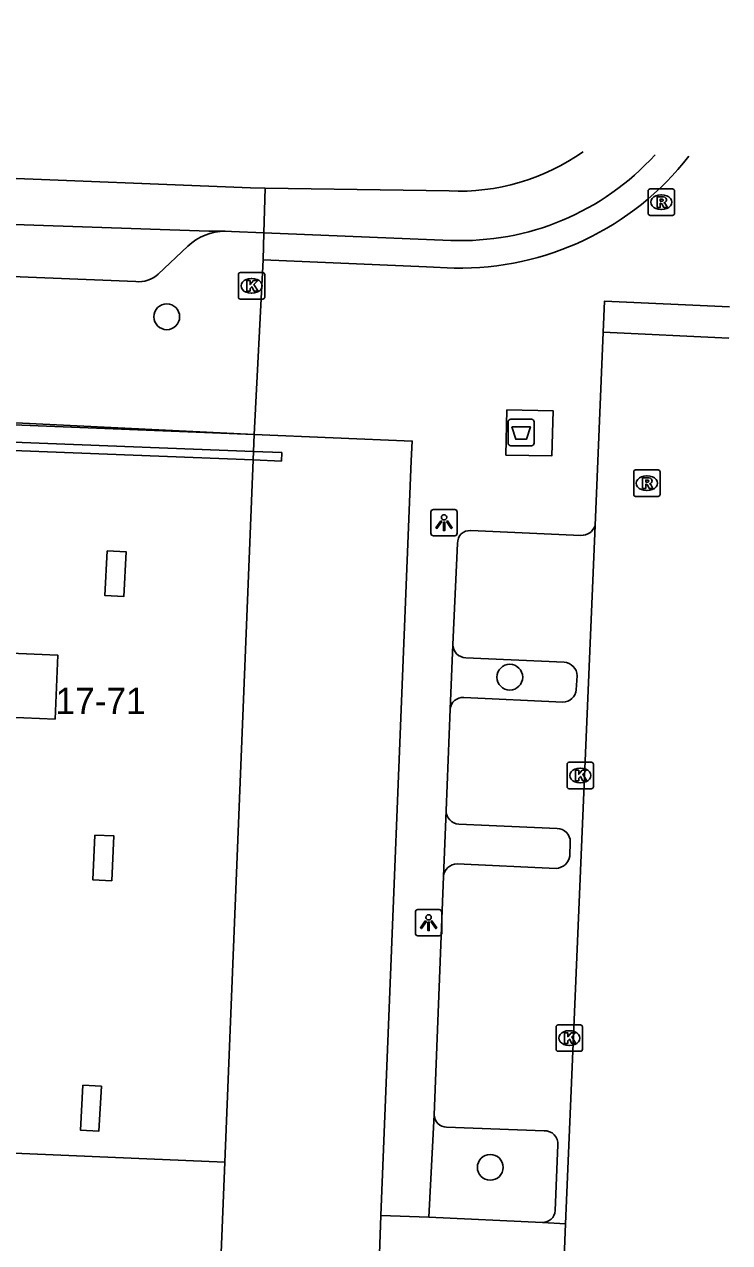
# Model space of a CAD drawing. Extents: x 160891 to 161384, y 386490 to 386907.
# Drawn here: x 161269.97 to 161296.73, y 386854.36 to 386900.56 of the extents above; entities that cross this region are included whole.
import ezdxf

# ---------------------------------------------------------------- set-up
doc = ezdxf.new("R2010")
doc.units = 0
for name, color, linetype in [('IMGEO_Afval_apart_plaats', 7, 'Continuous'), ('IMGEO_Boom', 7, 'Continuous'), ('IMGEO_Hek', 7, 'Continuous'), ('IMGEO_Kolk', 7, 'Continuous'), ('IMGEO_Lichtpunt', 7, 'Continuous'), ('IMGEO_Muur', 7, 'Continuous'), ('IMGEO_Pand', 7, 'Continuous'), ('IMGEO_Pand_nummerreeks', 7, 'Continuous'), ('IMGEO_Pand_overbouw', 7, 'Continuous'), ('IMGEO_Parkeervlak_open', 7, 'Continuous'), ('IMGEO_Rijbaan_lokaal_gesloten', 7, 'Continuous'), ('IMGEO_Rijbaan_lokaal_open', 7, 'Continuous'), ('IMGEO_Rioolput', 7, 'Continuous'), ('IMGEO_Voetpad_gesloten', 7, 'Continuous'), ('IMGEO_Voetpad_open', 7, 'Continuous')]:
    doc.layers.add(name, color=color, linetype=linetype)

msp = doc.modelspace()

# ---------------------------------------------------------------- linework, layer by layer
at = {"layer": 'IMGEO_Afval_apart_plaats'}
for p, q in [((161288.323, 386884.683), (161288.323, 386885.483)), ((161288.323, 386885.483), (161288.323, 386884.683)), ((161288.423, 386885.583), (161289.213, 386885.583)), ((161289.213, 386885.583), (161288.423, 386885.583)), ((161289.313, 386885.483), (161289.313, 386884.683)), ((161289.313, 386884.683), (161289.313, 386885.483)), ((161289.213, 386884.583), (161288.423, 386884.583)), ((161288.423, 386884.583), (161289.213, 386884.583))]:
    msp.add_line(p, q, dxfattribs=at)
msp.add_lwpolyline([(161288.466, 386885.297), (161289.17, 386885.297), (161289.021, 386884.827), (161288.615, 386884.827), (161288.466, 386885.297)], dxfattribs=at)
for centre, start, end in [((161288.423, 386885.483), 90, 180), ((161288.423, 386885.483), 90, 180), ((161289.213, 386885.483), 0, 90), ((161289.213, 386885.483), 360, 90), ((161288.423, 386884.683), 180, 270), ((161288.423, 386884.683), 180, 270), ((161289.213, 386884.683), 270, 0), ((161289.213, 386884.683), 270, 0)]:
    msp.add_arc(centre, 0.1, start, end, dxfattribs=at)
at = {"layer": 'IMGEO_Boom'}
for centre in [(161275.373, 386889.471), (161288.387, 386875.804), (161287.645, 386857.215)]:
    msp.add_circle(centre, 0.489, dxfattribs=at)
at = {"layer": 'IMGEO_Hek'}
msp.add_lwpolyline([(161284.645, 386884.014), (161283.497, 386855.383)], dxfattribs=at)
at = {"layer": 'IMGEO_Kolk'}
for p, q in [((161278.09, 386890.218), (161278.09, 386891.07)), ((161278.165, 386891.144), (161279.017, 386891.144)), ((161278.578, 386890.924), (161278.603, 386890.924)), ((161279.091, 386891.07), (161279.091, 386890.218)), ((161278.601, 386890.364), (161278.576, 386890.364)), ((161279.017, 386890.144), (161278.165, 386890.144)), ((161290.56, 386871.649), (161290.56, 386872.501)), ((161290.635, 386872.575), (161291.487, 386872.575)), ((161291.048, 386872.355), (161291.073, 386872.355)), ((161291.561, 386872.501), (161291.561, 386871.649)), ((161291.071, 386871.795), (161291.046, 386871.795)), ((161291.487, 386871.575), (161290.635, 386871.575)), ((161290.143, 386861.691), (161290.143, 386862.543)), ((161290.218, 386862.617), (161291.07, 386862.617)), ((161291.144, 386862.543), (161291.144, 386861.691)), ((161290.631, 386862.397), (161290.656, 386862.397)), ((161291.07, 386861.617), (161290.218, 386861.617)), ((161290.654, 386861.837), (161290.629, 386861.837))]:
    msp.add_line(p, q, dxfattribs=at)
for points in [[(161278.09, 386890.218), (161278.09, 386891.07)], [(161278.165, 386891.144), (161279.017, 386891.144)], [(161278.411, 386890.844), (161278.534, 386890.844), (161278.534, 386890.693), (161278.664, 386890.844), (161278.828, 386890.844), (161278.682, 386890.693), (161278.835, 386890.444), (161278.683, 386890.444), (161278.598, 386890.608), (161278.534, 386890.541), (161278.534, 386890.444), (161278.411, 386890.444), (161278.411, 386890.844)], [(161279.091, 386891.07), (161279.091, 386890.218)], [(161279.017, 386890.144), (161278.165, 386890.144)], [(161290.56, 386871.649), (161290.56, 386872.501)], [(161290.635, 386872.575), (161291.487, 386872.575)], [(161290.881, 386872.275), (161291.004, 386872.275), (161291.004, 386872.124), (161291.134, 386872.275), (161291.298, 386872.275), (161291.152, 386872.124), (161291.305, 386871.875), (161291.153, 386871.875), (161291.068, 386872.039), (161291.004, 386871.972), (161291.004, 386871.875), (161290.881, 386871.875), (161290.881, 386872.275)], [(161291.561, 386872.501), (161291.561, 386871.649)], [(161291.487, 386871.575), (161290.635, 386871.575)], [(161290.143, 386861.691), (161290.143, 386862.543)], [(161290.218, 386862.617), (161291.07, 386862.617)], [(161291.144, 386862.543), (161291.144, 386861.691)], [(161290.464, 386862.317), (161290.587, 386862.317), (161290.587, 386862.166), (161290.717, 386862.317), (161290.881, 386862.317), (161290.735, 386862.166), (161290.888, 386861.917), (161290.736, 386861.917), (161290.651, 386862.081), (161290.587, 386862.014), (161290.587, 386861.917), (161290.464, 386861.917), (161290.464, 386862.317)], [(161291.07, 386861.617), (161290.218, 386861.617)]]:
    msp.add_lwpolyline(points, dxfattribs=at)
for centre, start, end in [((161278.167, 386891.068), 91.552, 178.448), ((161278.167, 386891.068), 91.552, 178.448), ((161279.015, 386891.068), 1.552, 88.448), ((161279.015, 386891.068), 1.552, 88.448), ((161278.167, 386890.22), 181.552, 268.448), ((161278.167, 386890.22), 181.552, 268.448), ((161279.015, 386890.22), 271.552, 358.448), ((161279.015, 386890.22), 271.552, 358.448), ((161290.637, 386872.499), 91.552, 178.448), ((161290.637, 386872.499), 91.552, 178.448), ((161291.485, 386872.499), 1.552, 88.448), ((161291.485, 386872.499), 1.552, 88.448), ((161290.637, 386871.651), 181.552, 268.448), ((161290.637, 386871.651), 181.552, 268.448), ((161291.485, 386871.651), 271.552, 358.448), ((161291.485, 386871.651), 271.552, 358.448), ((161290.22, 386862.541), 91.552, 178.448), ((161290.22, 386862.541), 91.552, 178.448), ((161291.068, 386862.541), 1.552, 88.448), ((161291.068, 386862.541), 1.552, 88.448), ((161290.22, 386861.693), 181.552, 268.448), ((161290.22, 386861.693), 181.552, 268.448), ((161291.068, 386861.693), 271.552, 358.448), ((161291.068, 386861.693), 271.552, 358.448)]:
    msp.add_arc(centre, 0.0765, start, end, dxfattribs=at)
for centre, major_axis, ratio, start_param, end_param in [((161278.577, 386890.644), (-0.387, 0.002), 0.722429, 4.712389, 7.853982), ((161278.602, 386890.644), (-0.39, 0.002), 0.717154, 1.570796, 4.712389), ((161291.047, 386872.075), (-0.387, 0.002), 0.722429, 4.712389, 7.853982), ((161291.072, 386872.075), (-0.39, 0.002), 0.717154, 1.570796, 4.712389), ((161290.63, 386862.117), (-0.387, 0.002), 0.722429, 4.712389, 7.853982), ((161290.655, 386862.117), (-0.39, 0.002), 0.717154, 1.570796, 4.712389)]:
    msp.add_ellipse(centre, major_axis=major_axis, ratio=ratio, start_param=start_param, end_param=end_param, dxfattribs=at)
at = {"layer": 'IMGEO_Lichtpunt'}
for p, q in [((161285.395, 386882.068), (161285.395, 386881.261)), ((161285.395, 386882.068), (161285.395, 386881.261)), ((161286.297, 386882.163), (161285.489, 386882.163)), ((161286.297, 386882.163), (161285.489, 386882.163)), ((161286.391, 386881.261), (161286.391, 386882.068)), ((161286.391, 386881.261), (161286.391, 386882.068)), ((161285.489, 386881.167), (161286.297, 386881.167)), ((161285.489, 386881.167), (161286.297, 386881.167)), ((161284.808, 386866.898), (161284.808, 386866.091)), ((161284.808, 386866.898), (161284.808, 386866.091)), ((161285.71, 386866.993), (161284.902, 386866.993)), ((161285.71, 386866.993), (161284.902, 386866.993)), ((161285.804, 386866.091), (161285.804, 386866.898)), ((161285.804, 386866.091), (161285.804, 386866.898)), ((161284.902, 386865.997), (161285.71, 386865.997)), ((161284.902, 386865.997), (161285.71, 386865.997))]:
    msp.add_line(p, q, dxfattribs=at)
for points in [[(161285.769, 386881.732), (161285.808, 386881.704), (161285.62, 386881.442), (161285.582, 386881.469), (161285.769, 386881.732)], [(161285.871, 386881.684), (161285.918, 386881.684), (161285.918, 386881.362), (161285.871, 386881.362), (161285.871, 386881.684)], [(161285.981, 386881.704), (161286.019, 386881.731), (161286.206, 386881.469), (161286.167, 386881.441), (161285.981, 386881.704)], [(161285.182, 386866.562), (161285.221, 386866.534), (161285.033, 386866.272), (161284.995, 386866.299), (161285.182, 386866.562)], [(161285.284, 386866.514), (161285.331, 386866.514), (161285.331, 386866.192), (161285.284, 386866.192), (161285.284, 386866.514)], [(161285.394, 386866.534), (161285.432, 386866.561), (161285.619, 386866.299), (161285.58, 386866.271), (161285.394, 386866.534)]]:
    msp.add_lwpolyline(points, dxfattribs=at)
for centre in [(161285.894, 386881.866), (161285.307, 386866.696)]:
    msp.add_circle(centre, 0.0994, dxfattribs=at)
for centre, start, end in [((161285.489, 386882.068), 90, 180), ((161285.489, 386882.068), 90, 180), ((161286.297, 386882.068), 0, 90), ((161286.297, 386882.068), 0, 90), ((161285.489, 386881.261), 180, 270), ((161285.489, 386881.261), 180, 270), ((161286.297, 386881.261), 270, 0), ((161286.297, 386881.261), 270, 360), ((161284.902, 386866.898), 90, 180), ((161284.902, 386866.898), 90, 180), ((161285.71, 386866.898), 0, 90), ((161285.71, 386866.898), 0, 90), ((161284.902, 386866.091), 180, 270), ((161284.902, 386866.091), 180, 270), ((161285.71, 386866.091), 270, 0), ((161285.71, 386866.091), 270, 360)]:
    msp.add_arc(centre, 0.0946, start, end, dxfattribs=at)
at = {"layer": 'IMGEO_Muur'}
for points in [[(161268.567, 386884.752), (161278.663, 386884.36)], [(161278.65, 386884.04), (161268.554, 386884.432)], [(161278.65, 386884.04), (161278.663, 386884.36)], [(161278.663, 386884.36), (161279.736, 386884.318), (161279.724, 386883.998), (161278.65, 386884.04)]]:
    msp.add_lwpolyline(points, dxfattribs=at)
at = {"layer": 'IMGEO_Pand'}
for points in [[(161222.369, 386886.248), (161221.375, 386860.939), (161221.275, 386860.943), (161221.078, 386856.403), (161221.066, 386856.099), (161221.271, 386856.091), (161221.965, 386856.062), (161221.919, 386854.943), (161229.279, 386854.644), (161238.505, 386854.269), (161238.86, 386863.105), (161248.886, 386860.967), (161254.82, 386859.706), (161254.804, 386859.3), (161254.641, 386855.168), (161257.979, 386855.044), (161267.366, 386854.695), (161267.493, 386857.839), (161277.574, 386857.417), (161277.385, 386852.718), (161283.395, 386852.488)], [(161273.109, 386880.597), (161273.827, 386880.563), (161273.745, 386878.865), (161273.027, 386878.899), (161273.109, 386880.597)], [(161268.243, 386876.619), (161268.307, 386876.617), (161268.249, 386876.768), (161271.239, 386876.642), (161271.137, 386874.214), (161268.151, 386874.333), (161268.226, 386874.47), (161268.157, 386874.473), (161268.243, 386876.619)], [(161272.649, 386869.817), (161273.366, 386869.782), (161273.284, 386868.084), (161272.566, 386868.119), (161272.649, 386869.817)], [(161272.189, 386860.326), (161272.892, 386860.289), (161272.802, 386858.591), (161272.099, 386858.628), (161272.189, 386860.326)]]:
    msp.add_lwpolyline(points, dxfattribs=at)
at = {"layer": 'IMGEO_Pand_overbouw'}
msp.add_lwpolyline([(161268.597, 386885.494), (161268.594, 386885.414), (161268.567, 386884.752), (161268.554, 386884.432), (161268.249, 386876.768), (161271.239, 386876.642), (161271.137, 386874.214), (161268.151, 386874.333), (161267.493, 386857.839), (161277.574, 386857.417), (161278.65, 386884.04), (161278.663, 386884.36), (161278.689, 386885.003)], close=True, dxfattribs=at)
at = {"layer": 'IMGEO_Parkeervlak_open'}
for points in [[(161290.445, 386876.371), (161286.716, 386876.537)], [(161290.902, 386875.327), (161290.948, 386875.86)], [(161286.642, 386875.03), (161290.395, 386874.859)], [(161290.183, 386870.06), (161286.454, 386870.23)], [(161290.661, 386869.015), (161290.68, 386869.559)], [(161286.385, 386868.722), (161290.145, 386868.551)], [(161289.691, 386858.597), (161285.989, 386858.735)], [(161290.109, 386855.573), (161290.208, 386858.067)]]:
    msp.add_lwpolyline(points, dxfattribs=at)
for centre, radius, start, end in [((161286.732, 386877.037), 0.5, 178.7551, 268.1361), ((161290.415, 386875.839), 0.533, 2.277, 86.8189), ((161286.602, 386874.559), 0.473, 85.1814, 175.6322), ((161290.409, 386875.353), 0.494, 268.4026, 357.0162), ((161286.479, 386870.739), 0.509, 179.6262, 267.1532), ((161290.193, 386869.573), 0.487, 358.3454, 91.1954), ((161290.115, 386869.103), 0.553, 273.0723, 350.853), ((161286.392, 386868.201), 0.522, 90.7175, 174.9974), ((161286.003, 386859.218), 0.484, 181.3596, 268.3971), ((161289.728, 386858.116), 0.483, 354.2201, 94.3572), ((161289.622, 386855.609), 0.488, 270.3229, 355.761)]:
    msp.add_arc(centre, radius, start, end, dxfattribs=at)
at = {"layer": 'IMGEO_Rijbaan_lokaal_gesloten'}
for points in [[(161123.263, 386900.56), (161248.069, 386895.57), (161278.544, 386894.358), (161279.11, 386894.349)], [(161279.11, 386894.349), (161279.059, 386892.659)], [(161286.088, 386894.243), (161279.11, 386894.349)], [(161277.593, 386892.717), (161276.971, 386892.717), (161258.887, 386893.342)], [(161279.059, 386892.659), (161277.832, 386892.705), (161277.593, 386892.717)], [(161286.148, 386892.369), (161279.059, 386892.659)]]:
    msp.add_lwpolyline(points, dxfattribs=at)
for centre, radius, start, end in [((161286.454, 386902.445), 8.211, 267.4462, 305.0109), ((161286.549, 386902.289), 9.928, 267.6839, 317.7351)]:
    msp.add_arc(centre, radius, start, end, dxfattribs=at)
at = {"layer": 'IMGEO_Rijbaan_lokaal_open'}
for points in [[(161291.625, 386881.556), (161291.93, 386888.882)], [(161296.697, 386888.665), (161296.697, 386888.665), (161291.93, 386888.882)], [(161291.625, 386881.556), (161290.502, 386855.078)], [(161283.395, 386852.488), (161283.497, 386855.383)], [(161283.497, 386855.383), (161285.322, 386855.328)], [(161285.322, 386855.328), (161289.625, 386855.121)], [(161289.625, 386855.121), (161290.502, 386855.078)], [(161290.502, 386855.078), (161290.382, 386852.207)]]:
    msp.add_lwpolyline(points, dxfattribs=at)
at = {"layer": 'IMGEO_Rioolput'}
for p, q in [((161293.635, 386893.391), (161293.635, 386894.243)), ((161293.71, 386894.317), (161294.562, 386894.317)), ((161294.123, 386894.097), (161294.148, 386894.097)), ((161294.636, 386894.243), (161294.636, 386893.391)), ((161294.146, 386893.537), (161294.121, 386893.537)), ((161294.562, 386893.317), (161293.71, 386893.317)), ((161293.087, 386882.735), (161293.087, 386883.587)), ((161293.162, 386883.661), (161294.014, 386883.661)), ((161293.575, 386883.441), (161293.6, 386883.441)), ((161294.088, 386883.587), (161294.088, 386882.735)), ((161293.598, 386882.881), (161293.573, 386882.881)), ((161294.014, 386882.661), (161293.162, 386882.661))]:
    msp.add_line(p, q, dxfattribs=at)
for points in [[(161293.635, 386893.391), (161293.635, 386894.243)], [(161293.71, 386894.317), (161294.562, 386894.317)], [(161294.224, 386894.015), (161293.972, 386894.017), (161293.972, 386893.617)], [(161294.15, 386893.936), (161294.096, 386893.936), (161294.096, 386893.855)], [(161294.636, 386894.243), (161294.636, 386893.391)], [(161293.972, 386893.617), (161294.096, 386893.617), (161294.096, 386893.779), (161294.107, 386893.779)], [(161294.096, 386893.855), (161294.148, 386893.855)], [(161294.154, 386893.75), (161294.225, 386893.617), (161294.365, 386893.617), (161294.3, 386893.743)], [(161294.562, 386893.317), (161293.71, 386893.317)], [(161293.087, 386882.735), (161293.087, 386883.587)], [(161293.162, 386883.661), (161294.014, 386883.661)], [(161293.676, 386883.359), (161293.424, 386883.361), (161293.424, 386882.961)], [(161294.088, 386883.587), (161294.088, 386882.735)], [(161293.424, 386882.961), (161293.548, 386882.961), (161293.548, 386883.123), (161293.559, 386883.123)], [(161293.602, 386883.28), (161293.548, 386883.28), (161293.548, 386883.199)], [(161293.548, 386883.199), (161293.6, 386883.199)], [(161293.606, 386883.094), (161293.677, 386882.961), (161293.817, 386882.961), (161293.752, 386883.087)], [(161294.014, 386882.661), (161293.162, 386882.661)]]:
    msp.add_lwpolyline(points, dxfattribs=at)
for centre, radius, start, end in [((161293.712, 386894.241), 0.0765, 91.552, 178.448), ((161293.712, 386894.241), 0.0765, 91.552, 178.448), ((161294.156, 386893.84), 0.0964, 77.0061, 93.1865), ((161294.17, 386893.897), 0.0378, 276.6634, 79.6772), ((161294.223, 386893.905), 0.109, 350.3612, 89.416), ((161294.56, 386894.241), 0.0765, 1.552, 88.448), ((161294.56, 386894.241), 0.0765, 1.552, 88.448), ((161294.106, 386893.726), 0.0533, 26.0293, 88.6989), ((161294.132, 386894.044), 0.19, 274.7715, 282.9687), ((161294.221, 386893.905), 0.112, 277.5842, 350.9817), ((161294.205, 386893.69), 0.108, 29.5134, 73.7905), ((161293.712, 386893.393), 0.0765, 181.552, 268.448), ((161293.712, 386893.393), 0.0765, 181.552, 268.448), ((161294.56, 386893.393), 0.0765, 271.552, 358.448), ((161294.56, 386893.393), 0.0765, 271.552, 358.448), ((161293.164, 386883.585), 0.0765, 91.552, 178.448), ((161293.164, 386883.585), 0.0765, 91.552, 178.448), ((161293.675, 386883.249), 0.109, 350.3612, 89.416), ((161294.012, 386883.585), 0.0765, 1.552, 88.448), ((161294.012, 386883.585), 0.0765, 1.552, 88.448), ((161293.558, 386883.07), 0.0533, 26.0293, 88.6989), ((161293.584, 386883.388), 0.19, 274.7715, 282.9687), ((161293.608, 386883.184), 0.0964, 77.0061, 93.1865), ((161293.622, 386883.241), 0.0378, 276.6634, 79.6772), ((161293.673, 386883.249), 0.112, 277.5842, 350.9817), ((161293.657, 386883.034), 0.108, 29.5134, 73.7905), ((161293.164, 386882.737), 0.0765, 181.552, 268.448), ((161293.164, 386882.737), 0.0765, 181.552, 268.448), ((161294.012, 386882.737), 0.0765, 271.552, 358.448), ((161294.012, 386882.737), 0.0765, 271.552, 358.448)]:
    msp.add_arc(centre, radius, start, end, dxfattribs=at)
for centre, major_axis, ratio, start_param, end_param in [((161294.122, 386893.817), (-0.387, 0.002), 0.722429, 4.712389, 7.853982), ((161294.147, 386893.817), (-0.39, 0.002), 0.717154, 1.570796, 4.712389), ((161293.574, 386883.161), (-0.387, 0.002), 0.722429, 4.712389, 7.853982), ((161293.599, 386883.161), (-0.39, 0.002), 0.717154, 1.570796, 4.712389)]:
    msp.add_ellipse(centre, major_axis=major_axis, ratio=ratio, start_param=start_param, end_param=end_param, dxfattribs=at)
at = {"layer": 'IMGEO_Voetpad_gesloten'}
msp.add_lwpolyline([(161288.243, 386884.223), (161288.281, 386885.938), (161290.038, 386885.903), (161289.983, 386884.198), (161288.243, 386884.223)], dxfattribs=at)
at = {"layer": 'IMGEO_Voetpad_open'}
for points in [[(161279.059, 386892.659), (161279.034, 386891.63)], [(161275.046, 386891.089), (161276.17, 386892.15)], [(161279.034, 386891.63), (161278.689, 386885.003)], [(161286.28, 386891.319), (161285.229, 386891.364), (161279.034, 386891.63)], [(161258.81, 386891.423), (161274.2, 386890.804)], [(161291.93, 386888.882), (161291.979, 386890.06), (161296.728, 386889.843)], [(161222.369, 386886.248), (161222.396, 386887.248), (161239.793, 386886.567), (161249.896, 386886.171), (161268.594, 386885.414), (161278.689, 386885.003)], [(161278.689, 386885.003), (161284.686, 386884.758), (161284.645, 386884.014), (161283.497, 386855.383)], [(161286.903, 386881.36), (161291.087, 386881.182)], [(161286.232, 386877.048), (161286.409, 386880.878)], [(161286.131, 386874.595), (161286.232, 386877.048)], [(161285.97, 386870.742), (161286.131, 386874.595)], [(161285.872, 386868.246), (161285.97, 386870.742)], [(161285.519, 386859.207), (161285.872, 386868.246)], [(161285.322, 386855.328), (161285.519, 386859.207)]]:
    msp.add_lwpolyline(points, dxfattribs=at)
for centre, radius, start, end in [((161286.498, 386902.319), 11.002, 268.8671, 322.1008), ((161277.62, 386890.58), 2.137, 90.723, 132.727), ((161274.309, 386891.879), 1.08, 264.2072, 313.028), ((161291.109, 386881.725), 0.543, 267.73, 341.8815), ((161286.86, 386880.91), 0.453, 84.5982, 183.9929)]:
    msp.add_arc(centre, radius, start, end, dxfattribs=at)

# ---------------------------------------------------------------- texts
at = {"layer": 'IMGEO_Pand_nummerreeks'}
msp.add_text('17-71', height=1, dxfattribs=at).set_placement((161271.151, 386874.405))

doc.saveas('drawing.dxf')
